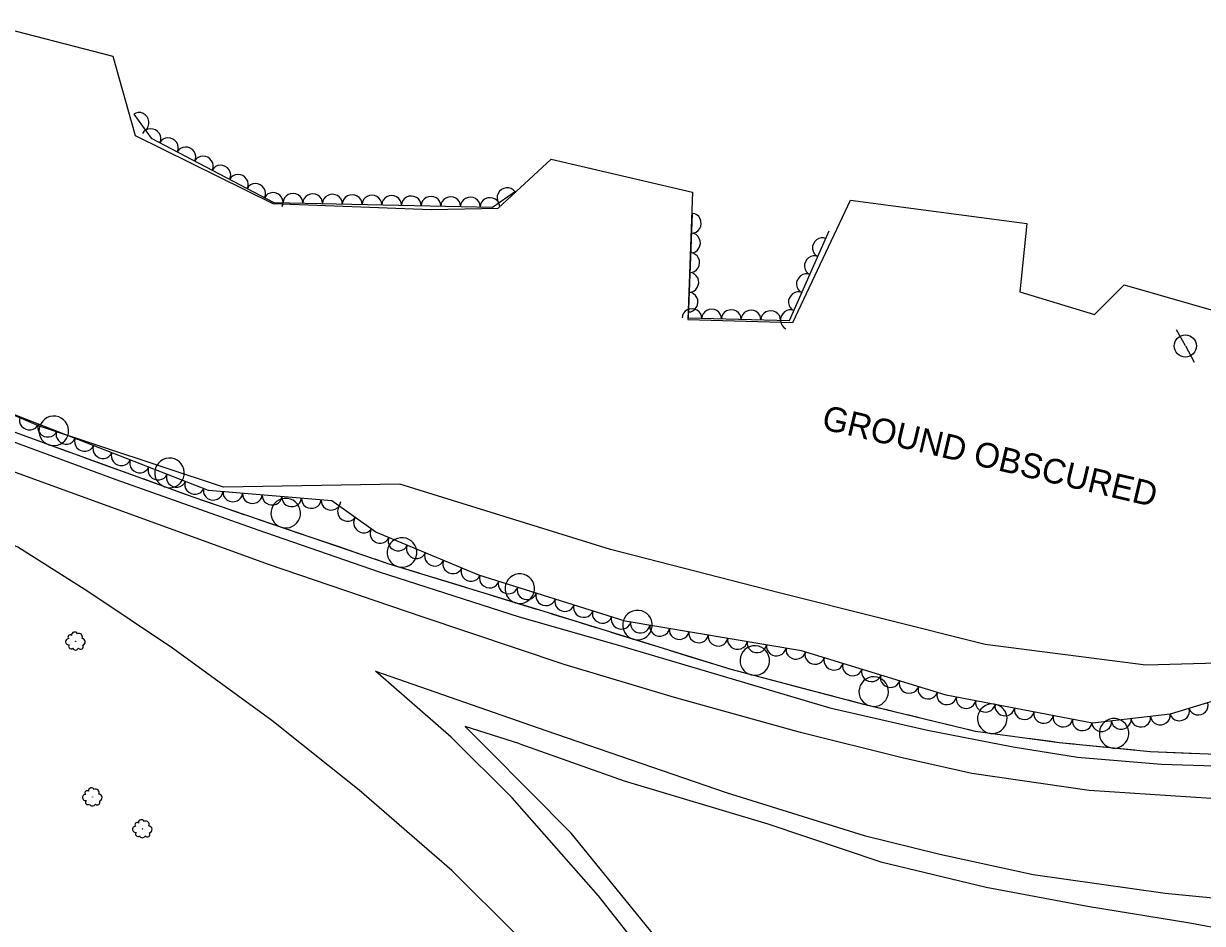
# Model space of a CAD drawing. Extents: x 1746719 to 1766531, y 631721 to 662391.
# Drawn here: x 1755693 to 1755932.2, y 647698.7 to 647881.2 of the extents above; entities that cross this region are included whole.
import ezdxf

# ---------------------------------------------------------------- set-up
doc = ezdxf.new("R2010")
doc.units = 0
for name, color, linetype in [('SURVEY - AERIAL SURVEY - Photo Control - Points - Elevations', 7, 'Continuous'), ('SURVEY - AERIAL SURVEY - Photo Control - Points - Locators', 7, 'Continuous'), ('SURVEY - AERIAL SURVEY - Photo Control - Points - Numbers', 7, 'Continuous'), ('SURVEY - AERIAL SURVEY - Photo Control with Text', 7, 'Continuous'), ('SURVEY - CENTERLINE - Existing Roads - Development', 7, 'Continuous')]:
    doc.layers.add(name, color=color, linetype=linetype)

msp = doc.modelspace()

# ---------------------------------------------------------------- linework, layer by layer
at = {"layer": 'SURVEY - AERIAL SURVEY - Photo Control - Points - Elevations'}
for points in [[(1755554.25, 647849.09), (1755569.88, 647842.85), (1755590.05, 647834.71), (1755615.81, 647825.09), (1755639.46, 647815.95), (1755661.16, 647807.4), (1755682.51, 647799.46), (1755711.72, 647788.73), (1755740.49, 647778.55), (1755765.17, 647770.04), (1755793.53, 647760.9), (1755813.21, 647755.28), (1755834.98, 647748.86), (1755856.62, 647742.43), (1755876.41, 647737.89), (1755893.76, 647734.53), (1755906.87, 647732.43), (1755923.9, 647731.01), (1755943.14, 647730.41)], [(1755933.94, 647724.01), (1755909.21, 647725.62), (1755885.43, 647729.12), (1755871.24, 647732.25), (1755850.64, 647737.4), (1755825.06, 647744.52), (1755802.7, 647751.22), (1755773.89, 647760.91), (1755742.69, 647771.5), (1755709.44, 647783.61), (1755669.48, 647798.07), (1755637.47, 647810.73), (1755587.52, 647829.96), (1755545.85, 647846.79)], [(1755840.58, 647610.43), (1755842.28, 647619.97), (1755840.2, 647628.96), (1755836.03, 647639.29), (1755823.78, 647657.34), (1755815.52, 647669.03), (1755803.22, 647684.9), (1755792.97, 647696.45), (1755779.87, 647709.45), (1755761.11, 647725.73), (1755743.38, 647739.86), (1755723.18, 647754.54), (1755706.04, 647766), (1755691.84, 647774.99), (1755672.19, 647783.03), (1755638.35, 647795.66), (1755603.54, 647809.02), (1755565.61, 647824.24), (1755521.37, 647842.24)], [(1755821.91, 647688.71), (1755809.66, 647704.29), (1755792.16, 647724.14), (1755779.75, 647736.46), (1755764.39, 647749.83), (1755798.99, 647737.79), (1755835.54, 647725.25), (1755863.53, 647716.54), (1755878.93, 647712.76), (1755897.83, 647708.62), (1755924.62, 647704.8), (1755947.5, 647702.61)], [(1756091.77, 647707.05), (1756084.15, 647702.97), (1756066.08, 647697.04), (1756030.39, 647683.71), (1755987.24, 647668.56), (1755948.58, 647654.5), (1755910.34, 647639.95), (1755882.03, 647629.6), (1755870.9, 647625.35), (1755862.91, 647622.49), (1755858.65, 647638.01), (1755848.97, 647656.36), (1755829.38, 647685.89), (1755804.13, 647717.01), (1755787.2, 647734.01), (1755782.62, 647738.66)], [(1755793.72, 647735.09), (1755782.62, 647738.66)], [(1755793.72, 647735.09), (1755814.83, 647727.61), (1755844, 647718.86), (1755866.96, 647711.17), (1755888.33, 647706.02), (1755908.88, 647702.16), (1755929.63, 647698.82), (1755937.54, 647697.31)]]:
    msp.add_lwpolyline(points, dxfattribs=at)
at = {"layer": 'SURVEY - AERIAL SURVEY - Photo Control - Points - Locators'}
for points in [[(1755957.04, 647752.08), (1755920.7, 647751.04), (1755888.14, 647755.29), (1755846.3, 647765.75), (1755812.07, 647774.57), (1755769.33, 647787.8), (1755733.57, 647787.15), (1755696.04, 647799.65), (1755659.31, 647815.47), (1755644.01, 647825.95), (1755645.24, 647835.28), (1755637.43, 647867.65), (1755685.37, 647881.22), (1755711.13, 647874.62)], [(1755711.13, 647874.62), (1755715.61, 647858.55), (1755743.56, 647844.73), (1755775.67, 647843.48), (1755789.27, 647843.8), (1755800.07, 647853.69), (1755828.75, 647847), (1755827.81, 647821.19), (1755849.06, 647820.59), (1755860.8, 647845.41), (1755896.56, 647840.65), (1755895.13, 647826.78), (1755910.33, 647822.18), (1755916.35, 647828.24), (1755943.19, 647820.52)]]:
    msp.add_lwpolyline(points, dxfattribs=at)
at = {"layer": 'SURVEY - AERIAL SURVEY - Photo Control - Points - Numbers'}
for points in [[(1756312.65, 647817.39), (1756266.31, 647805.31), (1756221.82, 647792.33), (1756182.88, 647780.7), (1756150.91, 647771.08), (1756099.81, 647755.02), (1756047.27, 647741.62), (1756023.4, 647736.48), (1756005.99, 647734.86), (1755976.66, 647732.84), (1755945.14, 647732.56), (1755921.57, 647733.5), (1755903.16, 647735.35), (1755886.15, 647737.64), (1755863.47, 647743.12), (1755836.55, 647750.17), (1755799.48, 647761.67), (1755767.19, 647771.59), (1755727.39, 647785.14), (1755687.49, 647799.63), (1755668.54, 647807.22)], [(1755702.37, 647794.23), (1755693.72, 647797.37)], [(1755709.79, 647791.53), (1755705.38, 647793.14)], [(1755714.21, 647789.93), (1755709.79, 647791.53)], [(1755725.87, 647785.7), (1755717.22, 647788.84)], [(1755733.33, 647783.12), (1755728.89, 647784.63)], [(1755737.78, 647781.6), (1755733.33, 647783.12)], [(1755749.52, 647777.61), (1755740.81, 647780.57)], [(1755757, 647775.06), (1755752.55, 647776.57)], [(1755761.45, 647773.54), (1755757, 647775.06)], [(1755773.25, 647769.73), (1755767.19, 647771.59), (1755764.48, 647772.51)], [(1755780.8, 647767.41), (1755776.3, 647768.79)], [(1755785.29, 647766.03), (1755780.8, 647767.41)], [(1755797.14, 647762.39), (1755788.35, 647765.09)], [(1755804.69, 647760.05), (1755800.2, 647761.44)], [(1755809.18, 647758.66), (1755804.69, 647760.05)], [(1755821.02, 647754.99), (1755812.24, 647757.71)], [(1755828.57, 647752.65), (1755824.08, 647754.04)], [(1755833.06, 647751.26), (1755828.57, 647752.65)], [(1755845.01, 647747.96), (1755836.55, 647750.17), (1755836.11, 647750.31)], [(1755852.65, 647745.96), (1755848.1, 647747.15)], [(1755857.2, 647744.77), (1755852.65, 647745.96)], [(1755869.22, 647741.73), (1755863.47, 647743.12), (1755860.29, 647743.96)], [(1755876.9, 647739.88), (1755872.33, 647740.98)], [(1755881.47, 647738.77), (1755876.9, 647739.88)], [(1755893.66, 647736.63), (1755886.15, 647737.64), (1755884.58, 647738.02)], [(1755901.49, 647735.58), (1755896.84, 647736.2)], [(1755906.16, 647735.05), (1755903.16, 647735.35), (1755901.49, 647735.58)], [(1755918.5, 647733.81), (1755909.35, 647734.73)], [(1755926.38, 647733.3), (1755921.69, 647733.49)], [(1755931.08, 647733.12), (1755926.38, 647733.3)]]:
    msp.add_lwpolyline(points, dxfattribs=at)
for centre, start, end in [((1755699.11, 647798.6), 3.3123, 3.2983), ((1755722.61, 647790.07), 3.3123, 3.2983), ((1755746.18, 647781.91), 4.4604, 4.4464), ((1755769.77, 647773.93), 6.1892, 6.1752), ((1755793.67, 647766.59), 6.1892, 6.1752), ((1755817.56, 647759.2), 6.0436, 6.0296), ((1755841.36, 647752.01), 8.592, 8.578), ((1755865.5, 647745.72), 9.6706, 9.6566), ((1755889.55, 647740.21), 15.6187, 15.6047), ((1755914.27, 647737.25), 17.5061, 17.4922)]:
    msp.add_arc(centre, 3, start, end, dxfattribs=at)
at = {"layer": 'SURVEY - AERIAL SURVEY - Photo Control with Text'}
for points in [[(1755715.36, 647862.86), (1755718.85, 647858), (1755743.79, 647844.96), (1755788.12, 647844.01), (1755792.79, 647847.22)], [(1755945.65, 647747.19), (1755925.68, 647741.11), (1755909.88, 647739.28), (1755880.19, 647744.96), (1755850.84, 647753.97), (1755815.05, 647760.02), (1755785.34, 647769.32), (1755764.45, 647778.04), (1755755.52, 647784.41), (1755730.53, 647786.53), (1755691.66, 647801.65), (1755657.97, 647815.63), (1755641.88, 647825.79), (1755644.06, 647837.79), (1755637.7, 647861.97)], [(1755828.69, 647842.71), (1755827.82, 647821.51), (1755848.4, 647820.99), (1755856.49, 647839.2)]]:
    msp.add_lwpolyline(points, dxfattribs=at)
for centre in [(1755703.55, 647755.92), (1755706.98, 647724.31), (1755717.13, 647717.86)]:
    msp.add_circle(centre, 0.022, dxfattribs=at)
for centre, radius, start, end in [((1755702.43, 647756.79), 0.433, 49.5277, 228.2734), ((1755703.34, 647757.16), 0.631, 27.4116, 184.2005), ((1755704.2, 647756.8), 0.719, 336.4643, 113.9885), ((1755702.14, 647755.83), 0.629, 89.5484, 282.9681), ((1755702.6, 647754.87), 0.479, 132.1671, 309.4862), ((1755703.51, 647754.81), 0.679, 207.4541, 334.2998), ((1755704.54, 647754.84), 0.527, 217.613, 32.6133), ((1755704.77, 647755.8), 0.714, 287.3601, 83.1986), ((1755706.77, 647725.56), 0.631, 27.4116, 184.2005), ((1755707.62, 647725.19), 0.719, 336.4643, 113.9885), ((1755705.57, 647724.23), 0.629, 89.5484, 282.9681), ((1755705.86, 647725.18), 0.433, 49.5277, 228.2734), ((1755706.03, 647723.26), 0.479, 132.1671, 309.4862), ((1755707.97, 647723.23), 0.527, 217.613, 32.6133), ((1755708.2, 647724.2), 0.714, 287.3601, 83.1986), ((1755706.94, 647723.2), 0.679, 207.4541, 334.2998), ((1755716.01, 647718.72), 0.433, 49.5277, 228.2734), ((1755716.92, 647719.1), 0.631, 27.4116, 184.2005), ((1755717.77, 647718.74), 0.719, 336.4643, 113.9885), ((1755715.71, 647717.77), 0.629, 89.5484, 282.9681), ((1755716.18, 647716.8), 0.479, 132.1671, 309.4862), ((1755717.08, 647716.75), 0.679, 207.4541, 334.2998), ((1755718.11, 647716.77), 0.527, 217.613, 32.6133), ((1755718.34, 647717.74), 0.714, 287.3601, 83.1986)]:
    msp.add_arc(centre, radius, start, end, dxfattribs=at)
for centre, major_axis in [((1755716.52, 647861.23), (1.17, -1.62)), ((1755718.87, 647857.99), (1.77, -0.93)), ((1755722.41, 647856.14), (1.77, -0.93)), ((1755725.95, 647854.28), (1.77, -0.93)), ((1755729.5, 647852.43), (1.77, -0.93)), ((1755733.04, 647850.58), (1.77, -0.93)), ((1755736.59, 647848.72), (1.77, -0.93)), ((1755740.13, 647846.87), (1.77, -0.93)), ((1755791.03, 647846.01), (1.65, 1.13)), ((1755743.68, 647845.02), (1.77, -0.93)), ((1755747.66, 647844.88), (2, -0.04)), ((1755751.66, 647844.79), (2, -0.04)), ((1755755.66, 647844.71), (2, -0.04)), ((1755759.66, 647844.62), (2, -0.04)), ((1755763.66, 647844.53), (2, -0.04)), ((1755767.66, 647844.45), (2, -0.04)), ((1755771.66, 647844.36), (2, -0.04)), ((1755775.66, 647844.28), (2, -0.04)), ((1755779.66, 647844.19), (2, -0.04)), ((1755783.65, 647844.11), (2, -0.04)), ((1755787.65, 647844.02), (2, -0.04)), ((1755828.6, 647840.71), (-0.08, -2)), ((1755828.44, 647836.72), (-0.08, -2)), ((1755854.97, 647835.79), (0.81, 1.83)), ((1755828.28, 647832.72), (-0.08, -2)), ((1755853.35, 647832.13), (0.81, 1.83)), ((1755828.11, 647828.72), (-0.08, -2)), ((1755851.73, 647828.47), (0.81, 1.83)), ((1755827.95, 647824.73), (-0.08, -2)), ((1755850.1, 647824.82), (0.81, 1.83)), ((1755828.6, 647821.49), (2, -0.05)), ((1755832.6, 647821.39), (2, -0.05)), ((1755836.6, 647821.29), (2, -0.05)), ((1755840.6, 647821.19), (2, -0.05)), ((1755844.59, 647821.08), (2, -0.05)), ((1755848.48, 647821.16), (0.81, 1.83)), ((1755694.12, 647800.69), (-1.86, 0.73)), ((1755697.85, 647799.24), (-1.86, 0.73)), ((1755701.58, 647797.79), (-1.86, 0.73)), ((1755705.31, 647796.34), (-1.86, 0.73)), ((1755709.03, 647794.89), (-1.86, 0.73)), ((1755712.76, 647793.44), (-1.86, 0.73)), ((1755716.49, 647791.99), (-1.86, 0.73)), ((1755720.22, 647790.54), (-1.86, 0.73)), ((1755723.94, 647789.09), (-1.86, 0.73)), ((1755727.67, 647787.64), (-1.86, 0.73)), ((1755731.46, 647786.45), (-1.99, 0.17)), ((1755735.45, 647786.11), (-1.99, 0.17)), ((1755739.43, 647785.77), (-1.99, 0.17)), ((1755743.42, 647785.44), (-1.99, 0.17)), ((1755747.4, 647785.1), (-1.99, 0.17)), ((1755751.39, 647784.76), (-1.99, 0.17)), ((1755755.38, 647784.42), (-1.99, 0.17)), ((1755758.66, 647782.17), (-1.63, 1.16)), ((1755761.92, 647779.85), (-1.63, 1.16)), ((1755765.27, 647777.7), (-1.85, 0.77)), ((1755768.96, 647776.16), (-1.85, 0.77)), ((1755772.65, 647774.62), (-1.85, 0.77)), ((1755776.34, 647773.08), (-1.85, 0.77)), ((1755780.03, 647771.54), (-1.85, 0.77)), ((1755783.73, 647770), (-1.85, 0.77)), ((1755787.49, 647768.65), (-1.91, 0.6)), ((1755791.3, 647767.45), (-1.91, 0.6)), ((1755795.12, 647766.26), (-1.91, 0.6)), ((1755798.94, 647765.06), (-1.91, 0.6)), ((1755802.76, 647763.87), (-1.91, 0.6)), ((1755806.57, 647762.67), (-1.91, 0.6)), ((1755810.39, 647761.48), (-1.91, 0.6)), ((1755814.21, 647760.28), (-1.91, 0.6)), ((1755818.12, 647759.5), (-1.97, 0.33)), ((1755822.07, 647758.83), (-1.97, 0.33)), ((1755826.01, 647758.17), (-1.97, 0.33)), ((1755829.96, 647757.5), (-1.97, 0.33)), ((1755833.9, 647756.83), (-1.97, 0.33)), ((1755837.84, 647756.17), (-1.97, 0.33)), ((1755841.79, 647755.5), (-1.97, 0.33)), ((1755845.73, 647754.84), (-1.97, 0.33)), ((1755849.68, 647754.17), (-1.97, 0.33)), ((1755853.54, 647753.15), (-1.91, 0.59)), ((1755857.36, 647751.97), (-1.91, 0.59)), ((1755861.18, 647750.8), (-1.91, 0.59)), ((1755865.01, 647749.63), (-1.91, 0.59)), ((1755868.83, 647748.45), (-1.91, 0.59)), ((1755872.66, 647747.28), (-1.91, 0.59)), ((1755876.48, 647746.1), (-1.91, 0.59)), ((1755880.31, 647744.94), (-1.96, 0.38)), ((1755884.23, 647744.19), (-1.96, 0.38)), ((1755888.16, 647743.44), (-1.96, 0.38)), ((1755892.09, 647742.68), (-1.96, 0.38)), ((1755931.4, 647742.85), (-1.91, -0.58)), ((1755896.02, 647741.93), (-1.96, 0.38)), ((1755899.95, 647741.18), (-1.96, 0.38)), ((1755903.88, 647740.43), (-1.96, 0.38)), ((1755907.81, 647739.67), (-1.96, 0.38)), ((1755915.73, 647739.96), (-1.99, -0.23)), ((1755919.7, 647740.41), (-1.99, -0.23)), ((1755923.68, 647740.87), (-1.99, -0.23)), ((1755927.58, 647741.68), (-1.91, -0.58)), ((1755911.76, 647739.5), (-1.99, -0.23))]:
    msp.add_ellipse(centre, major_axis=major_axis, ratio=0.940188, start_param=0, end_param=3.141593, dxfattribs=at)
at = {"layer": 'SURVEY - CENTERLINE - Existing Roads - Development'}
for q in [(1755926.96, 647819.13), (1755930.51, 647812.52)]:
    msp.add_line((1755928.74, 647815.83), q, dxfattribs=at)
msp.add_circle((1755928.74, 647815.83), 2.25, dxfattribs=at)

# ---------------------------------------------------------------- texts
at = {"layer": 'SURVEY - AERIAL SURVEY - Photo Control - Points - Locators'}
msp.add_text('GROUND OBSCURED', height=5, rotation=346.7687, dxfattribs=at).set_placement((1755854.72, 647799.03))

doc.saveas('drawing.dxf')
